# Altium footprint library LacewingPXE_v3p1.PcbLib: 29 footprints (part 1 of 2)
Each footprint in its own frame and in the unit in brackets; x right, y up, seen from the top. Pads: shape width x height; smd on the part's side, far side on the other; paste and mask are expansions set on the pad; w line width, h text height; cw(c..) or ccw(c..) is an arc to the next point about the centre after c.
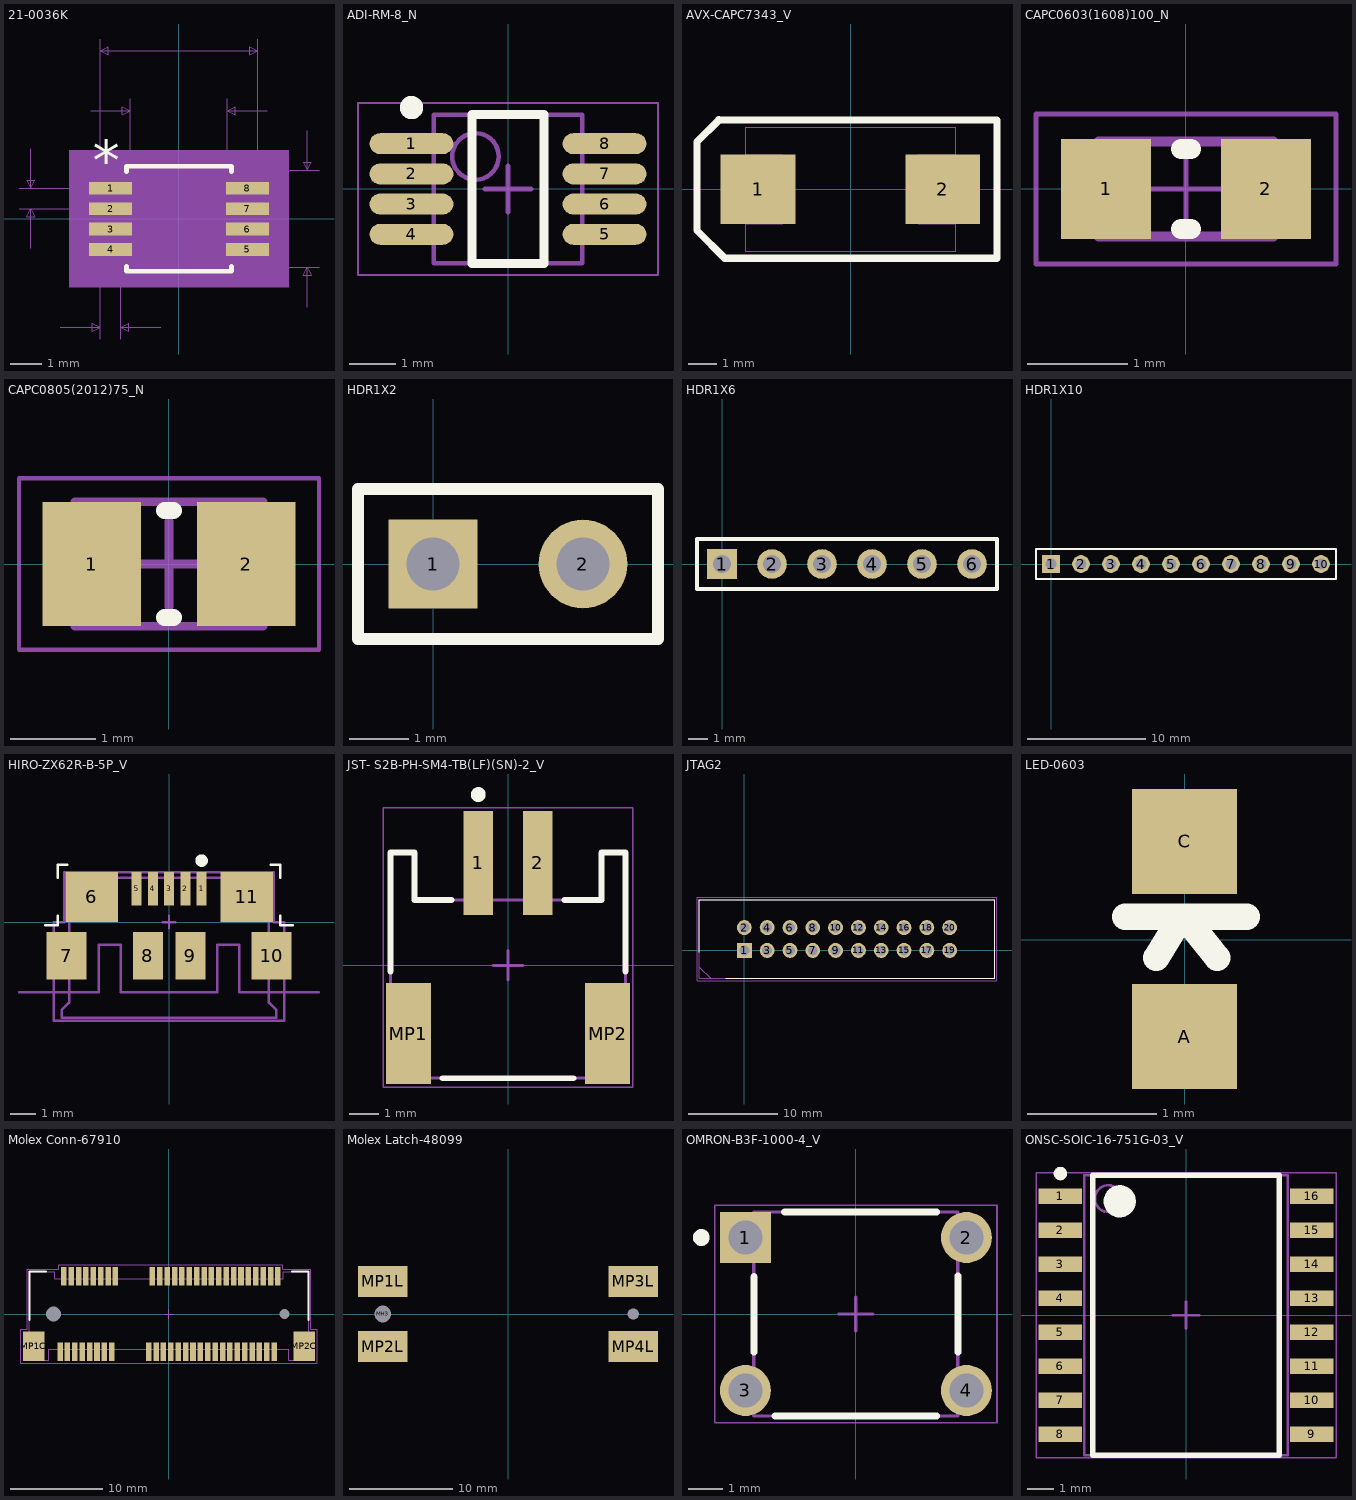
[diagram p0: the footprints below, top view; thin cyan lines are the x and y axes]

## 21-0036K [mil]
pads (8):
  rect 54x16 smd paste+0 mask+0: 1(-86,38.39) 2(-86,12.8) 3(-86,-12.8) 4(-86,-38.39) 5(86,-38.39) 6(86,-12.8) 7(86,12.8) 8(86,38.39)
Top Overlay:
  lines w6: -66,-59.49 -66,-66 66,-66 66,-59.49 ; -66,59.49 -66,66 66,66 66,59.49
  text "*" at -108.5,49.39 h50
Mechanical 5:
  region: 138,-86 -138,-86 -138,86 138,86
Mechanical 7:
  lines w1: -201,12.8 -86,12.8 ; -201,38.39 -86,38.39 ; -186,-37.2 -186,12.8 ; -186,88.39 -186,38.39 ; -149,-136 -99,-136 ; -111,136 -61,136 ; -99,-151 -99,0 -99,226 ; -73,-151 -73,0 ; -61,0 -61,151 ; -23,-136 -73,-136 ; 0,-61 176,-61 ; 0,61 176,61 ; 61,0 61,151 ; 99,0 99,226 ; 111,136 61,136 ; 161,-111 161,-61 ; 161,111 161,61 ; -186,12.8 -191,2.8 -181,2.8 -186,12.8 ; -186,38.39 -191,48.39 -181,48.39 -186,38.39 ; -99,-136 -109,-131 -109,-141 -99,-136 ; -99,211 99,211 ; -99,211 -89,216 -89,206 -99,211 ; -73,-136 -63,-131 -63,-141 -73,-136 ; -61,136 -71,141 -71,131 -61,136 ; 61,136 71,141 71,131 61,136 ; 99,211 89,216 89,206 99,211 ; 161,-61 156,-71 166,-71 161,-61 ; 161,61 156,71 166,71 161,61
  text "Default Padstyle: RX54Y16D0T" at -350,-261 h50
  text "Pin One Padstyle: RX54Y16D0T" at -350,-321 h50
  text "Alt 1 Padstyle: OX60Y90D30P" at -337.5,-501 h50
  text "Alt 2 Padstyle: OX90Y60D30P" at -337.5,-561 h50
  text "0.122in/3.099mm" at -93.75,156 h25
  text "0.198in/5.029mm" at -93.75,231 h25
  text "0.122in/3.099mm" at 181,-12.5 h25
  text "0.026in/0.65mm" at -381,13.09 h25
  text "0.026in/0.66mm" at -173.5,-181 h25
Mechanical 13:
  lines w0: -12,61 ccw(c0,61) 12,61
  lines w1: -99,-45.39 -99,-31.39 -61,-31.39 -61,-45.39 -99,-45.39 ; -99,-19.8 -99,-5.8 -61,-5.8 -61,-19.8 -99,-19.8 ; -99,5.8 -99,19.8 -61,19.8 -61,5.8 -99,5.8 ; -99,31.39 -99,45.39 -61,45.39 -61,31.39 -99,31.39 ; -61,-61 61,-61 61,61 -61,61 -61,-61 ; 61,-45.39 61,-31.39 99,-31.39 99,-45.39 61,-45.39 ; 61,-19.8 61,-5.8 99,-5.8 99,-19.8 61,-19.8 ; 61,5.8 61,19.8 99,19.8 99,5.8 61,5.8 ; 61,31.39 61,45.39 99,45.39 99,31.39 61,31.39
  text "*" at -58.5,8 h50
Mechanical 15:
  region: -71,-56.39 -123,-56.39 -123,56.39 -71,56.39 -71,71 71,71 71,56.39 123,56.39 123,-56.39 71,-56.39 71,-71 -71,-71
  lines w6: -123,-56.39 -123,56.39 -71,56.39 -71,71 71,71 71,56.39 123,56.39 123,-56.39 71,-56.39 71,-71 -71,-71 -71,-56.39 -123,-56.39
3D body: height 10, standoff 0, extent 0,0 10,10

## ADI-RM-8_N [mm] "SOP, 8-Leads, Body 3x3mm, Pitch 0.65mm, IPC Medium Density"
height 1.1
pads (8):
  oval 1.8x0.45 smd: 1(-2.075,0.975) 2(-2.075,0.325) 3(-2.075,-0.325) 4(-2.075,-0.975) 5(2.075,-0.975) 6(2.075,-0.325) 7(2.075,0.325) 8(2.075,0.975)
Top Overlay:
  circle w0.25: c-2.075,1.75 r0.125
  lines w0.2: -0.775,-1.6 -0.775,1.6 0.775,1.6 0.775,-1.6 -0.775,-1.6
Mechanical 13:
  circle w0.1: c-0.7,0.7 r0.5
  lines w0.1: -1.6,-1.6 -1.6,1.6 1.6,1.6 1.6,-1.6 -1.6,-1.6
Mechanical 15:
  lines w0.05: -3.225,-1.85 -3.225,1.85 3.225,1.85 3.225,-1.85 -3.225,-1.85
  lines w0.1: -0.5,0 0.5,0 ; 0,-0.5 0,0.5
3D body: height 1.1, standoff 0, extent -1.6,-1.6 1.6,1.6

## AVX-CAPC7343_V [mm] "SMT Capacitor, 2 Leads, Body 7.3x4.3mm"
pads (2):
  rect 2.6x2.4 smd: 1(-3.202,0.007) 2(3.198,0.007)
Top Overlay:
  lines w0.254: -4.575,2.4 -5.325,1.65 -5.325,-1.425 -4.362,-2.388 ; -4.572,2.413 5.08,2.406 ; -4.369,-2.388 5.08,-2.388 5.08,2.388
Mechanical 7:
  lines w0.025: -3.651,-1.192 -2.351,-1.192 -2.351,1.208 -3.651,1.208 ; 3.649,-1.192 2.349,-1.192 2.349,1.208 3.649,1.208 ; -3.651,-2.142 3.649,-2.142 3.649,2.158 -3.651,2.158 -3.651,-2.142
  text ".Designator" at -3.575,1.375 h0.6
  text ".Comment" at -3.575,-2.025 h0.6
3D body: height 0.3, standoff 0, extent 3.308,-0.855 3.512,0.915
3D body: height 0.3, standoff 0, extent -3.487,-0.869 -3.392,0.82
3D body: height 2.9, standoff 0, extent -3.464,-2.032 3.481,2.039
3D body: height 4.05, standoff 3.9, extent -2.468,-2.017 -1.993,2.005

## CAPC0603(1608)100_N [mm] "Chip Capacitor, Body 1.6x0.8mm, Height 1.0mm, IPC Medium Density"
height 1
pads (2):
  rect 0.9x1 smd: 1(-0.8,0) 2(0.8,0)
Top Overlay:
  lines w0.2: -0.05,-0.4 0.05,-0.4 ; -0.05,0.4 0.05,0.4
Mechanical 13:
  lines w0.1: -0.875,-0.475 0.875,-0.475 0.875,0.475 -0.875,0.475 -0.875,-0.475
Mechanical 15:
  lines w0.05: -0.475,0 0.475,0 ; 0,-0.475 0,0.475 ; -1.5,-0.75 1.5,-0.75 1.5,0.75 -1.5,0.75 -1.5,-0.75
3D body: height 1, standoff 0, extent 0.525,-0.475 0.875,0.475
3D body: height 1, standoff 0, extent -0.875,-0.475 -0.525,0.475
3D body: height 1, standoff 0, extent -0.525,-0.475 0.525,0.475

## CAPC0805(2012)75_N [mm] "Chip Capacitor, Body 2.0x1.2mm, Height 0.75mm, IPC Medium Density"
height 0.75
pads (2):
  rect 1.15x1.45 smd: 1(-0.9,0) 2(0.9,0)
Top Overlay:
  lines w0.2: -0.05,-0.625 0.05,-0.625 ; -0.05,0.625 0.05,0.625
Mechanical 13:
  lines w0.1: -1.1,-0.725 1.1,-0.725 1.1,0.725 -1.1,0.725 -1.1,-0.725
Mechanical 15:
  lines w0.05: -1.75,-1 1.75,-1 1.75,1 -1.75,1 -1.75,-1
  lines w0.1: -0.5,0 0.5,0 ; 0,-0.5 0,0.5
3D body: height 0.75, standoff 0, extent 0.6,-0.725 1.1,0.725
3D body: height 0.75, standoff 0, extent -1.1,-0.725 -0.6,0.725
3D body: height 0.75, standoff 0, extent -0.6,-0.725 0.6,0.725

## HDR1X2 [mm] "Connector; Header; 2 Position"
pads (2):
  rect 1.5x1.5 hole 0.9: 1(0,0)
  round 1.5 hole 0.9: 2(2.54,0)
Top Overlay:
  lines w0.2: -1.27,-1.27 -1.27,1.27 3.81,1.27 3.81,-1.27 -1.27,-1.27

## HDR1X6 [mm] "Connector; Header; 6 Position"
pads (6):
  rect 1.5x1.5 hole 0.9: 1(0,0)
  round 1.5 hole 0.9: 2(2.54,0) 3(5.08,0) 4(7.62,0) 5(10.16,0) 6(12.7,0)
Top Overlay:
  lines w0.2: -1.27,-1.27 13.97,-1.27 13.97,1.27 -1.27,1.27 -1.27,-1.27

## HDR1X10 [mm] "Connector; Header; 10 Position"
pads (10):
  rect 1.5x1.5 hole 0.9: 1(0,0)
  round 1.5 hole 0.9: 2(2.54,0) 3(5.08,0) 4(7.62,0) 5(10.16,0) 6(12.7,0) 7(15.24,0) 8(17.78,0) 9(20.32,0) 10(22.86,0)
Top Overlay:
  lines w0.2: -1.27,-1.27 -1.27,1.27 0.635,1.27 24.13,1.27 24.13,-1.27 -1.27,-1.27

## HIRO-ZX62R-B-5P_V [mm] "USB Micro-B R/A Connector"
height 2.65
pads (11):
  rect 0.4x1.35 smd: 1(1.3,1.338) 2(0.65,1.338) 3(0,1.338) 4(-0.65,1.338) 5(-1.3,1.338)
  rect 2.1x2 smd: 6(-3.1,1.012) 11(3.1,1.012)
  rect 1.6x1.9 smd: 7(-4.1,-1.338) 10(4.1,-1.338)
  rect 1.2x1.9 smd: 8(-0.85,-1.338) 9(0.85,-1.338)
Top Overlay:
  circle w0.25: c1.304,2.46 r0.125
  lines w0.1: -4.953,-0.127 -4.445,-0.127 -4.445,0.254 ; -4.445,1.778 -4.445,2.286 -4.064,2.286 ; 4.064,2.286 4.445,2.286 4.445,1.778 ; 4.445,0.254 4.445,-0.127 4.953,-0.127
Mechanical 1:
  lines w0.1: -6,-2.8 -2.82,-2.8 -2.82,-0.9 -1.92,-0.9 -1.92,-2.8 0,-2.8 1.92,-2.8 1.92,-0.9 2.82,-0.9 2.82,-2.8 6,-2.8
  text "Board edge" at 5.588,-2.667 h0.2
Mechanical 13:
  lines w0.1: -4,1.78 4,1.78 ; -4,1.78 4,1.78 ; -4,1.78 -4,-0.72 -4.572,-0.72 -4.572,-1.778 -4,-1.778 -4,-3.22 -4.3,-3.52 -4.3,-3.82 4.3,-3.82 4.3,-3.52 4,-3.22 4,-1.778 4.572,-1.778 4.572,-0.72 4,-0.72 4,1.78
Mechanical 15:
  lines w0.1: -0.254,0 0.254,0 ; 0,-0.254 0,0.254 ; -4.6,-3.937 4.6,-3.937 4.6,-2.8 4.6,0 4.2,0 4.2,2 -4.2,2 -4.2,0 -4.6,0 -4.6,-2.8 -4.6,-3.937
3D body "ZX62R-B-5P.stp": height 2.71, standoff -0.23, extent -4.4,-3.953 4.4,1.778

## JST- S2B-PH-SM4-TB(LF)(SN)-2_V [mm] "SMD, 2-Leads, Body 7.9x7.6mm, Pitch 2mm"
height 5.5
pads (4):
  rect 1x3.5 smd: 1(-1,3.45) 2(1,3.45)
  rect 1.5x3.4 smd: MP1(-3.35,-2.3) MP2(3.35,-2.3)
Top Overlay:
  circle w0.25: c-1,5.75 r0.125
  lines w0.2: -3.95,-0.2 -3.95,3.8 -3.15,3.8 -3.15,2.2 -1.9,2.2 ; -2.2,-3.8 2.2,-3.8 ; 1.9,2.2 3.15,2.2 3.15,3.8 3.95,3.8 3.95,-0.2
Mechanical 13:
  lines w0.1: -3.95,-3 -3.95,3.8 -3.15,3.8 -3.15,2.2 3.15,2.2 3.15,3.8 3.95,3.8 3.95,-3 3.45,-3 3.45,-3.8 -3.45,-3.8 -3.45,-3 -3.95,-3
Mechanical 15:
  lines w0.05: -4.2,-4.1 4.2,-4.1 4.2,5.3 -4.2,5.3 -4.2,-4.1
  lines w0.1: -0.5,0 0.5,0 ; 0,-0.5 0,0.5
3D body "S2B-PH-SM4-TB.STEP": height 5.6, standoff 0, extent -3.95,-3.8 3.95,4.8

## JTAG2 [mm] "Header, Vertical Shrouded, 100 mil pitch; 25 mil lead width, 20 pins, 2 rows, 10 pins per row, 1295 mil L X 346 mil W X 346 mil H body"
height 8.788
pads (20):
  rect 1.652x1.652 hole 1.101 paste-1.652: 1(0,0)
  round 1.652 hole 1.101 paste-1.652: 2(0,2.54) 3(2.54,0) 4(2.54,2.54) 5(5.08,0) 6(5.08,2.54) 7(7.62,0) 8(7.62,2.54) 9(10.16,0) 10(10.16,2.54) 11(12.7,0) 12(12.7,2.54) 13(15.24,0) 14(15.24,2.54) 15(17.78,0) 16(17.78,2.54) 17(20.32,0) 18(20.32,2.54) 19(22.86,0) 20(22.86,2.54)
Top Overlay:
  lines w0.127: -5.016,-0.195 -5.016,5.664 27.877,5.664 27.877,-3.124 -2.087,-3.124
Mechanical 11:
  lines w0.127: -5.016,-1.854 -3.746,-3.124 27.877,-3.124 27.877,5.664 -5.016,5.664 -5.016,-1.854
Mechanical 12:
  lines w0.025: -5.016,-3.124 -5.016,5.664 27.877,5.664 27.877,-3.124 -5.016,-3.124
Mechanical 15:
  circle w0.051: c0,0 r0.305
  lines w0.051: -0.406,0 0.406,0 ; 0,-0.406 0,0.406 ; -5.271,-3.378 -5.271,5.918 28.13,5.918 28.13,-3.378 -5.271,-3.378
3D body "TSS-110-01-G-D.step": height 8.89, standoff -3.3, extent -3.175,-3.556 26.035,5.918

## LED-0603 [mil] "LED-0603"
pads (2):
  rect 32x32 smd: A(0,-29.53) C(0,30)
Top Overlay:
  lines w8: -18.11,7 0,7 ; -8.6,-5.51 -1,7 ; 10,-5.51 0,7 ; 19,7 0,7

## Molex Conn-67910 [mm] "Board-to-Board Connector, SMT, Right Angle, Pitch 0.8mm, 52-Position, Female"
pads (56):
  rect 0.6x2 smd: 1(-11.8,-4.1) 2(-11.4,4.1) 3(-11,-4.1) 4(-10.6,4.1) 5(-10.2,-4.1) 6(-9.8,4.1) 7(-9.4,-4.1) 8(-9,4.1) 9(-8.6,-4.1) 10(-8.2,4.1) 11(-7.8,-4.1) 12(-7.4,4.1) 13(-7,-4.1) 14(-6.6,4.1) 15(-6.2,-4.1) 16(-5.8,4.1) 17(-2.2,-4.1) 18(-1.8,4.1) 19(-1.4,-4.1) 20(-1,4.1) 21(-0.6,-4.1) 22(-0.2,4.1) 23(0.2,-4.1) 24(0.6,4.1) 25(1,-4.1) 26(1.4,4.1) 27(1.8,-4.1) 28(2.2,4.1) 29(2.6,-4.1) 30(3,4.1) 31(3.4,-4.1) 32(3.8,4.1) 33(4.2,-4.1) 34(4.6,4.1) 35(5,-4.1) 36(5.4,4.1) 37(5.8,-4.1) 38(6.2,4.1) 39(6.6,-4.1) 40(7,4.1) 41(7.4,-4.1) 42(7.8,4.1) 43(8.2,-4.1) 44(8.6,4.1) 45(9,-4.1) 46(9.4,4.1) 47(9.8,-4.1) 48(10.2,4.1) 49(10.6,-4.1) 50(11,4.1) 51(11.4,-4.1) 52(11.8,4.1)
  round 1.3 hole 1.6 unplated: MH1(-12.5,0)
  round 0.8 hole 1.1 unplated: MH2(12.5,0)
  rect 2.3x3.2 smd: MP1C(-14.65,-3.5) MP2C(14.65,-3.5)
Top Overlay:
  lines w0.2: -15.125,-0.633 -15.125,4.6 -14.907,4.6 -13.338,4.6 ; 13.329,4.6 15.125,4.6 ; 15.125,-0.645 15.125,4.535
Mechanical 13:
  lines w0.1: -15.125,-3.8 -14.025,-3.8 ; -15.125,-3.798 -15.125,4.6 -14.907,4.6 -12.375,4.6 -12.375,3.799 ; -14.027,-5 -13,-5 -13,-3.8 13,-3.8 13,-5 14.01,-5 14.025,-4.985 14.025,-3.804 ; -14.025,-5 -14.025,-3.822 ; -12.375,3.8 12.375,3.8 12.375,4.601 ; 12.375,4.6 15.125,4.6 15.125,4.535 15.125,-3.796 ; 14.025,-3.8 15.125,-3.8
Mechanical 15:
  lines w0.1: -0.5,0 0.5,0 ; 0,-0.5 0,0.5 ; -16.05,-5.35 16.05,-5.35 16.05,-1.65 15.375,-1.65 15.375,4.85 12.35,4.85 12.35,5.35 -11.95,5.35 -11.95,4.85 -15.375,4.85 -15.375,-1.65 -16.05,-1.65 -16.05,-5.35
3D body: height 0.82, standoff 0.2, extent 12.35,3.8 15,4.5
3D body: height 0.82, standoff 0.2, extent 15,4.5 15,4.5
3D body: height 0.82, standoff 0.2, extent -15,3.7 -12.35,4.5
3D body: height 1.34, standoff 0.69, extent 12.1,-4.25 13.79,-3.7
3D body: height 1.34, standoff 0.69, extent -13.79,-4.25 -12.1,-3.7
3D body: height 5.6, standoff 4.54, extent -13.79,-5 -12.1,-3.7
3D body: height 5.6, standoff 4.54, extent 12.1,-5 13.79,-3.7
3D body: height 5.6, standoff 3.12, extent -15,-3.7 15,3.677
3D body: height 3.12, standoff 0, extent -15,-3.7 15,3.8

## Molex Latch-48099 [mm]
pads (6):
  round 1.3 hole 1.6 unplated: MH3(-12.1,0)
  round 0.8 hole 1.1 unplated: MH4(12.1,0)
  rect 4.8x3 smd: MP1L(-12.1,3.15) MP2L(-12.1,-3.15) MP3L(12.1,3.15) MP4L(12.1,-3.15)

## OMRON-B3F-1000-4_V [mm] "TH, 4-Leads, Body 6x6mm"
height 4.5
pads (4):
  rect 1.5x1.5 hole 1 paste+0: 1(-3.25,2.25)
  round 1.5 hole 1 paste+0: 2(3.25,2.25) 3(-3.25,-2.25) 4(3.25,-2.25)
Top Overlay:
  circle w0.25: c-4.55,2.25 r0.125
  lines w0.2: -3,-1.127 -3,1.1 ; -2.378,-3 2.378,-3 ; -2.1,3 2.378,3 ; 3,-1.127 3,1.127
Mechanical 13:
  lines w0.1: -3,-3 -3,3 3,3 3,-3 -3,-3
Mechanical 15:
  lines w0.05: -4.15,-3.2 -4.15,3.2 4.15,3.2 4.15,-3.2 -4.15,-3.2
  lines w0.1: -0.5,0 0.5,0 ; 0,-0.5 0,0.5
3D body: height 4.5, standoff 0, extent -3,-3 3,3

## ONSC-SOIC-16-751G-03_V [mm] "SOIC, 16-Leads, Body 10.45x7.6mm, Pitch 1.27mm"
height 2.65
pads (16):
  rect 1.62x0.58 smd: 1(-4.69,4.445) 2(-4.69,3.175) 3(-4.69,1.905) 4(-4.69,0.635) 5(-4.69,-0.635) 6(-4.69,-1.905) 7(-4.69,-3.175) 8(-4.69,-4.445) 9(4.69,-4.445) 10(4.69,-3.175) 11(4.69,-1.905) 12(4.69,-0.635) 13(4.69,0.635) 14(4.69,1.905) 15(4.69,3.175) 16(4.69,4.445)
Top Overlay:
  circle w0.25: c-4.69,5.285 r0.125
  circle w0.6: c-2.475,4.25 r0.3
  lines w0.2: -3.48,-5.225 -3.48,5.225 3.48,5.225 3.48,-5.225 -3.48,-5.225
Mechanical 13:
  circle w0.1: c-2.9,4.35 r0.5
  lines w0.1: -3.8,-5.225 -3.8,5.225 3.8,5.225 3.8,-5.225 -3.8,-5.225
Mechanical 15:
  lines w0.05: -5.6,-5.325 -5.6,5.325 5.6,5.325 5.6,-5.325 -5.6,-5.325
  lines w0.1: -0.5,0 0.5,0 ; 0,-0.5 0,0.5
3D body: height 2.65, standoff 0.1, extent -3.8,-5.225 3.8,5.225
